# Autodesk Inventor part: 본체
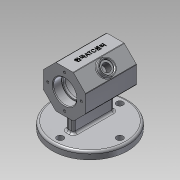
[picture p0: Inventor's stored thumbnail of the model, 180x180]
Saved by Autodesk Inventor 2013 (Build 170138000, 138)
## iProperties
Created: 2021-02
Part Number: 본체
Material: 알루미늄 6061
Document SubType Name: Modeling
Designer: default
Density: 2.71 g/cm^3
Mass: 558.81 g
Surface Area: 509.677 cm^2
Volume: 206.203 cm^3
Author: default
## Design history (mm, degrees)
sketch "스케치1"
  geometry: C1 r 52 at (0, 0); 1 further point
  constraints: 1 centre point, 1 coincident
  dimensions: "d0" = 104 diameter of C1
extrude "돌출1" new body sketch "스케치1" distance "d2" = 10; taper "d3" = 0 deg
sketch "스케치2" dims "d4" = 82
  geometry: C1 r 52 at (0, 0) reference; 1 further point
  constraints: 2 vertical alignment, 2 other
hole "구멍1" sketch "스케치2" at (0, 41) diameter "d6" = 9; stored, may be unused: countersink angle "d10" = 90 deg, drill point angle "d12" = 118 deg; dims "d7" = 6, "d8" = 4, "d9" = 2, "d11" = 8
sketch "스케치9"
  geometry: L1 (12.012, 33)-(-12.012, 33); L2 (-12.012, 33)-(-29, 49.988); L3 (-29, 49.988)-(-29, 74.012); L4 (-29, 74.012)-(-12.012, 91); L5 (-12.012, 91)-(12.012, 91); L6 (12.012, 91)-(29, 74.012); L7 (29, 74.012)-(29, 49.988); L8 (29, 49.988)-(12.012, 33); L9 (4.5, 0)-(-4.5, 0) reference; L10 (-52, 0)-(52, 0) reference; 3 further points
  constraints: 16 end point, 2 vertical alignment, 1 midpoint, 17 other
  dimensions: "d53" = 62 distance from line of L9 point (0, 62); "d54" = 91 distance between parallel lines of L10 L5
extrude "돌출4" join sketch "스케치9" stored distance "d55" = 70; taper "d56" = 0 deg
sketch "스케치10"
  geometry: L1 (-35, 74.012)-(-35, 49.988) reference; L2 (35, 49.988)-(35, 74.012) reference; L3 (-35, 62)-(35, 62); L4 (-35, 91)-(-35, 74.012) reference; L5 (35, 74.012)-(35, 91) reference; L6 (-35, 78)-(-23.3, 78); L7 (-23, 77.7)-(-23, 76); L8 (-23, 76)-(-20, 76); L9 (-20, 76)-(-20, 81); L10 (-17, 84)-(17, 84); L11 (20, 81)-(20, 76); L12 (20, 76)-(23, 76); L13 (23, 76)-(23, 77.7); L14 (23.3, 78)-(35, 78); A1 r 0.3 centre (-23.3, 77.7) between (-23, 77.7) and (-23.3, 78); A2 r 0.3 centre (23.3, 77.7) between (23.3, 78) and (23, 77.7); A3 r 3 centre (-17, 81) between (-17, 84) and (-20, 81); A4 r 3 centre (17, 81) between (20, 81) and (17, 84); 4 further points
  constraints: 20 end point, 8 point on circle, 8 point on line, 8 tangent, 6 parallel, 4 centre point, 4 equal length, 3 perpendicular, 2 equal radius, 2 midpoint
  dimensions: "d65" = 32 diameter of L6 L3; "d67" = 28 diameter of L8 L3; "d68" = 44 diameter of L10 L3; "d69" = 12 distance of L6.start point (-23, 78); "d70" = 40 distance of point (-20, 84) point (20, 84); "d71" = 0.3 radius of A1; "d72" = 3 radius of A3
revolve "회전2" sketch "스케치10" stored, may be unused: angle "d73" = 90 deg
chamfer "모따기2" distance "d74" = 1; stored, may be unused: second distance "d75" = 2, angle "d76" = 45 deg
sketch "스케치11" dims "d77" = 46
  geometry: C1 r 17 at (0, 62) reference; 2 further points
  constraints: 2 vertical alignment, 2 other
hole "구멍3" sketch "스케치11" at (0, 85) diameter "d79" = 3.242; stored, may be unused: countersink angle "d83" = 90 deg, drill point angle "d85" = 118 deg; dims "d80" = 8, "d81" = 4, "d82" = 2, "d84" = 10
sketch "스케치12"
  geometry: L1 (-5, -28)-(5, -28); L2 (5, -28)-(5, 28); L3 (5, 28)-(-5, 28); L4 (-5, 28)-(-5, -28); L5 (-5, -28)-(5, 28); L6 (5, -28)-(-5, 28); C1 r 52 at (0, 0) reference
  constraints: 12 end point, 2 midpoint, 2 parallel, 1 horizontal, 1 perpendicular
  dimensions: "d89" = 10 distance of L2.end L3.end; "d91" = 56 distance of L1.end L2.end
extrude "돌출5" join sketch "스케치12" stored distance "d92" = 70; taper "d93" = 0 deg
sketch "스케치13"
  geometry: L1 (-24.024, 70)-(0, 70) reference; L2 (-41.012, 70)-(-41.012, 0) reference; C1 r 10 at (-12.012, 35); 1 further point
  constraints: 1 centre point
  dimensions: "d94" = 29 distance from line of L2 C1.centre; "d95" = 35 distance from line of L1 C1.centre; "d96" = 20 diameter of C1
extrude "돌출6" join sketch "스케치13" distance "d97" = 5; taper "d98" = 0 deg
sketch "스케치14"
  geometry: C1 r 10 at (0, 0) reference; 1 further point
hole "구멍4" sketch "스케치14" at (0, 0) diameter "d99" = 10.917; stored, may be unused: countersink angle "d103" = 90 deg, drill point angle "d105" = 118 deg; dims "d100" = 8, "d101" = 16, "d102" = 2, "d104" = 10
chamfer "모따기3" distance "d106" = 1; stored, may be unused: second distance "d107" = 2, angle "d108" = 45 deg
fillet "모깎기1" dims "d109" = 1
fillet "모깎기2" dims "d110" = 1
fillet "모깎기3" dims "d111" = 3
fillet "모깎기4" dims "d112" = 3
fillet "모깎기5" dims "d113" = 3
sketch "스케치15"
  geometry: L1 (0, 70)-(23.196, 70) reference; L2 (-17.109, 0)-(-17.109, 70) reference; 2 further points
  constraints: 1 other
  dimensions: "d114" = 29 distance from line of L2 point (11.891, 35); "d115" = 35 distance from line of L1 point (11.891, 35)
feature "엠보싱1" sketch "스케치15" dims "d53" = 62, "d54" = 91, "d116" = 0.5, "d117" = 0
node "솔리드1"
pattern_circular "원형 패턴1" dims angle "d14" = 360 deg
pattern_circular "원형 패턴3" dims angle "d87" = 360 deg
mirror "대칭2"
